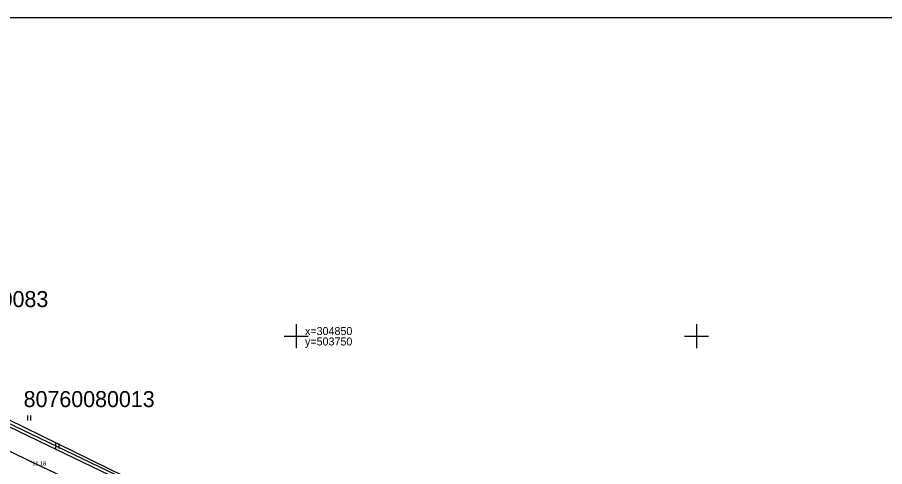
# Model space of a CAD drawing. Extents: x 503353 to 504004, y 304662 to 305049.
# Drawn here: x 503715.2 to 503823.5, y 304833.7 to 304889.8 of the extents above; entities that cross this region are included whole.
import ezdxf

# ---------------------------------------------------------------- set-up
doc = ezdxf.new("R2010")
doc.units = 0
for name, color, linetype in [('59', 7, 'Continuous'), ('APGR_SARK_####_####_#', 7, 'Continuous'), ('CELI_CMAL_####_####_#', 7, 'Continuous'), ('ELEK_VADP_ZSPR_####_#', 7, 'Continuous'), ('GEOD_ELEM_####_####_#', 7, 'Continuous'), ('GEOD_KORD_####_TKST_#', 7, 'Continuous'), ('RAMI_PLAN_####_TKST_#', 7, 'Continuous'), ('RAMI_UZMR_####_####_#', 7, 'Continuous'), ('RELJ_AATZ_####_TKST_#', 7, 'Continuous'), ('RELJ_ELEM_####_####_#', 7, 'Continuous'), ('RELJ_HORZ_PAMT_####_#', 7, 'Continuous'), ('TERT_ELEM_####_####_#', 7, 'Continuous')]:
    doc.layers.add(name, color=color, linetype=linetype)

msp = doc.modelspace()

# ---------------------------------------------------------------- linework, layer by layer
at = {"layer": 'APGR_SARK_####_####_#'}
msp.add_line((503703.16, 304844.41), (503751.85, 304821.07), dxfattribs=at)
at = {"layer": 'CELI_CMAL_####_####_#'}
msp.add_lwpolyline([(503693.84, 304845.69), (503716.88, 304834.38), (503754.06, 304816.88), (503763.57, 304812.02), (503796.62, 304795.13), (503820.7, 304783.38)], dxfattribs=at)
at = {"layer": 'ELEK_VADP_ZSPR_####_#'}
for points in [[(503695.59, 304847.68), (503717.76, 304837)], [(503717.76, 304837), (503742.33, 304825.16), (503762.71, 304815.31)]]:
    msp.add_lwpolyline(points, dxfattribs=at)
at = {"layer": 'GEOD_ELEM_####_####_#'}
for p, q in [((503750, 304851.5), (503750, 304850)), ((503800, 304851.5), (503800, 304850)), ((503748.5, 304850), (503750, 304850)), ((503750, 304850), (503750, 304848.5)), ((503750, 304850), (503751.5, 304850)), ((503798.5, 304850), (503800, 304850)), ((503800, 304850), (503800, 304848.5)), ((503800, 304850), (503801.5, 304850))]:
    msp.add_line(p, q, dxfattribs=at)
at = {"layer": 'RAMI_PLAN_####_TKST_#'}
msp.add_lwpolyline([(503840.28, 304747.19), (503643.1, 304747.19), (503643.1, 304889.79), (503840.28, 304889.79)], close=True, dxfattribs=at)
at = {"layer": 'RAMI_UZMR_####_####_#'}
msp.add_lwpolyline([(503694.65, 304834.72), (503842.28, 304765.87), (503906.26, 304738.48), (503957.92, 304717.01), (503965.11, 304709.04), (503977.82, 304703.92), (503984.98, 304722), (503973.64, 304724.03), (503962.96, 304726.51), (503949.45, 304730.69), (503911.59, 304746.5), (503899.78, 304752.82), (503825.92, 304784.83), (503697.43, 304847.71)], dxfattribs=at)
at = {"layer": 'RELJ_ELEM_####_####_#'}
msp.add_circle((503716.88, 304834.38), 0.05, dxfattribs=at)
at = {"layer": 'RELJ_HORZ_PAMT_####_#'}
msp.add_spline([(503717.47, 304822.61), (503711.32, 304828.85), (503696.84, 304836.46), (503685.42, 304842.03), (503668.5, 304854.13)], degree=3, dxfattribs=at)
at = {"layer": 'TERT_ELEM_####_####_#'}
for p, q in [((503716.5, 304839.5), (503716.5, 304840.1)), ((503716.9, 304839.5), (503716.9, 304840.1)), ((503720, 304836), (503720, 304836.6)), ((503720.4, 304836), (503720.4, 304836.6))]:
    msp.add_line(p, q, dxfattribs=at)

# ---------------------------------------------------------------- texts
at = {"layer": '59'}
for s, p in [('80760080083', (503702.7, 304853.64)), ('80760080013', (503715.98, 304841.16))]:
    msp.add_text(s, height=2, dxfattribs=at).set_placement(p)
at = {"layer": 'GEOD_KORD_####_TKST_#'}
for s, p in [('   x=304850', (503750, 304850.15)), ('   y=503750', (503750, 304848.85))]:
    msp.add_text(s, height=1, dxfattribs=at).set_placement(p)
at = {"layer": 'RELJ_AATZ_####_TKST_#'}
msp.add_text(' 11.18', height=0.5, dxfattribs=at).set_placement((503716.88, 304833.88))

doc.saveas('drawing.dxf')
